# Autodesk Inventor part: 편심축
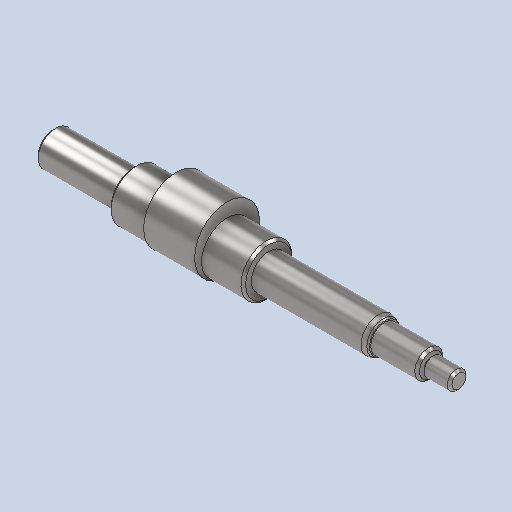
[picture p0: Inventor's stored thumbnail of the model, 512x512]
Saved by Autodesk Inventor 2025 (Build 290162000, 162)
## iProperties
Created: 2025-08
Part Number: 편심축
Material: 강철, 연강
Document SubType Name: Modeling
Designer: infra028
Density: 7.86 g/cm^3
Appearance: 기본값
Author: jhkim
Sending System: Autodesk Inventor 2026
Preprocessor: ST-DEVELOPER v20.1
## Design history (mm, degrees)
feature "솔리드1"
node "솔리드2"
